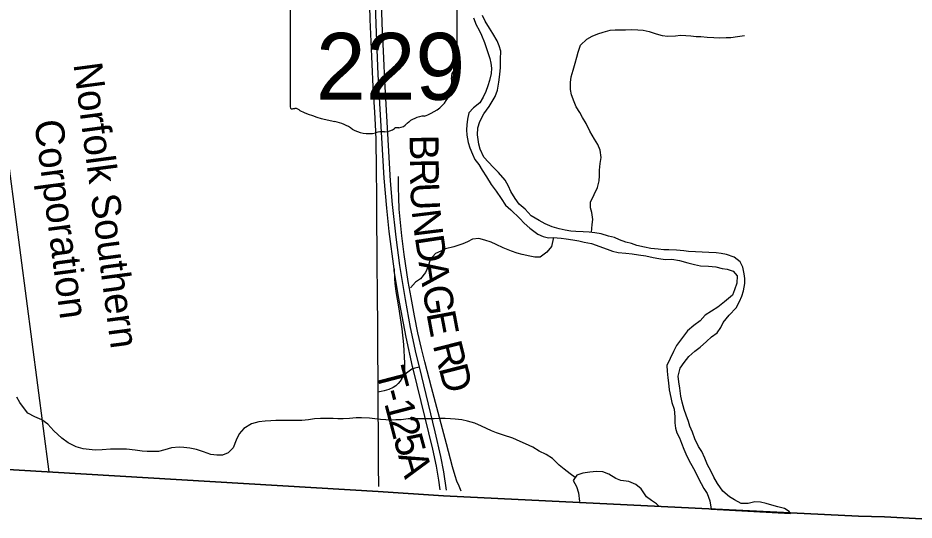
# Model space of a CAD drawing. Extents: x 1584893 to 1934202, y 663575 to 1091909.
# Drawn here: x 1804696 to 1814023, y 887388 to 892618 of the extents above; entities that cross this region are included whole.
import ezdxf

# ---------------------------------------------------------------- set-up
doc = ezdxf.new("R2010")
doc.units = 0
for name, color, linetype in [('GM_X_Adjacent_County', 7, 'Continuous'), ('GM_X_County', 7, 'Continuous'), ('GM_X_Interchange_Ramps', 7, 'Continuous'), ('GM_X_Major_River', 7, 'Continuous'), ('GM_X_Minor_River', 7, 'Continuous'), ('GM_X_Rail_Line', 7, 'Continuous'), ('GM_X_Rail_Line_Text', 7, 'Continuous'), ('GM_X_State_Location', 7, 'Continuous'), ('GM_X_State_Route', 7, 'Continuous'), ('GM_X_State_Shield', 7, 'Continuous'), ('GM_X_Township', 7, 'Continuous'), ('GM_X_Township_Road', 7, 'Continuous'), ('GM_X_Township_Road_Text', 7, 'Continuous'), ('GM_X_US_Route', 7, 'Continuous')]:
    doc.layers.add(name, color=color, linetype=linetype)

msp = doc.modelspace()

# ---------------------------------------------------------------- linework, layer by layer
at = {"layer": 'GM_X_Adjacent_County'}
msp.add_lwpolyline([(1760161.3, 891041.6), (1765804.4, 890576.9), (1771665.9, 890079.8), (1775268.9, 889747), (1775894.1, 889674), (1776031.5, 889657.9), (1778208.7, 889455.9), (1784657.2, 889013.6), (1789933.2, 888711.1), (1791146.1, 888682.4), (1797650.8, 888236.8), (1803655.1, 887971.5), (1808445, 887685), (1809126.3, 887642.5), (1809338.6, 887629.3), (1813443.3, 887428.9), (1813716.6, 887421.5), (1814360, 887388.3)], dxfattribs=at)
at = {"layer": 'GM_X_County'}
msp.add_lwpolyline([(1814360, 887388.3), (1813716.6, 887421.5), (1813443.3, 887428.9), (1809338.6, 887629.3), (1809126.3, 887642.5), (1808445, 887685), (1803655.1, 887971.5), (1797650.8, 888236.8), (1791146.1, 888682.4), (1789933.2, 888711.1), (1784657.2, 889013.6), (1778208.7, 889455.9), (1776031.5, 889657.9), (1775894.1, 889674), (1775268.9, 889747), (1771665.9, 890079.8), (1765804.4, 890576.9), (1760161.3, 891041.6)], dxfattribs=at)
at = {"layer": 'GM_X_Interchange_Ramps'}
for points in [[(1808611.1, 890004.3), (1808614.3, 889903.2), (1808617.8, 889853.2), (1808629.5, 889768.2), (1808656.8, 889609.2), (1808691, 889381.7), (1808707.8, 889218.1), (1808720.1, 889021.2), (1808719.6, 888955.5), (1808715.5, 888922.9), (1808706.6, 888891.3), (1808704.3, 888886.6), (1808692.3, 888861.7), (1808674.4, 888834.1), (1808653.1, 888809.1), (1808628.5, 888787.4), (1808601, 888769.4), (1808556.1, 888749), (1808509, 888734.3), (1808476.8, 888728), (1808441.7, 888721.2)], [(1808874.8, 888983.4), (1808857.4, 888978.3), (1808827.9, 888970.4), (1808809.5, 888963.6), (1808796.3, 888958.8), (1808781.1, 888950.7), (1808768, 888940.8), (1808740, 888917), (1808704.3, 888886.6)]]:
    msp.add_lwpolyline(points, dxfattribs=at)
at = {"layer": 'GM_X_Major_River'}
for points in [[(1809438, 892618.4), (1809467, 892545.7), (1809498.3, 892489.1), (1809519.6, 892438.6), (1809552.5, 892361.9), (1809573.7, 892299.4), (1809590.9, 892246.9), (1809606.2, 892196.6), (1809617.5, 892146.2), (1809624.7, 892093.9), (1809621.9, 892039.8), (1809604.8, 891967.8), (1809587.9, 891909.8), (1809565, 891851.9), (1809538.1, 891794.1), (1809503.1, 891732.4), (1809436.2, 891683.1), (1809389.3, 891629.6), (1809374.3, 891563.6), (1809367.4, 891505.5), (1809366.6, 891451.3), (1809369.8, 891397), (1809382.7, 891320.6), (1809397.9, 891266.2), (1809429, 891199.5), (1809452.3, 891145), (1809491.6, 891090.3), (1809526.8, 891033.6), (1809571.9, 890962.7), (1809620.8, 890881.7), (1809672, 890814.8), (1809724.9, 890735.8), (1809770.1, 890668.9), (1809827.5, 890617.9), (1809918.4, 890530.3), (1809963.8, 890479.5), (1810025.2, 890428.5), (1810108.5, 890367.1), (1810162.2, 890342.3), (1810218.2, 890329.4), (1810268.3, 890330.8), (1810348.5, 890325.6), (1810400.5, 890316.9), (1810472.5, 890307.8), (1810532.5, 890296.9), (1810588.5, 890284.1), (1810666.4, 890267), (1810828, 890210.5), (1810883.8, 890189.7), (1810941.7, 890174.8), (1811023.9, 890167.7), (1811087.9, 890162.7), (1811156, 890151.8), (1811230, 890138.7), (1811305.9, 890123.6), (1811365.9, 890112.7), (1811431.9, 890101.7), (1811502.1, 890104.8), (1811580.1, 890091.6), (1811668, 890068.3), (1811737.9, 890049.3), (1811801.9, 890036.3), (1811884.1, 890033.2), (1811960.1, 890024.1), (1812026.1, 890009.1), (1812076.1, 890002.4), (1812141.9, 889981.4), (1812183.3, 889930.7), (1812178.2, 889856.5), (1812153.1, 889784.6), (1812132.2, 889730.7), (1812051, 889661.5), (1811980, 889606.3), (1811915.2, 889563.1), (1811850.4, 889523.8), (1811797.4, 889464.4), (1811732.5, 889415.1), (1811663.6, 889359.9), (1811604.2, 889276.4)], [(1811972, 889337.5), (1812012.9, 889393.1), (1812035.8, 889445), (1812097.1, 889522.4), (1812170.4, 889599.7), (1812207.4, 889663.4), (1812230.3, 889721.3), (1812249.2, 889777.2), (1812260.4, 889853.3), (1812263.1, 889903.5), (1812255.8, 889953.7), (1812240.8, 890022.2), (1812211.6, 890078.8), (1812152.1, 890127.8), (1812072.3, 890155), (1812014.3, 890165.8), (1811964.3, 890170.6), (1811888.1, 890173.6), (1811816, 890178.7), (1811749.9, 890183.6), (1811675.8, 890186.6), (1811625.7, 890191.4), (1811549.6, 890198.4), (1811469.5, 890203.6), (1811419.4, 890204.3), (1811359.3, 890209.1), (1811283.3, 890218.2), (1811217.3, 890229.2), (1811137.3, 890248.4), (1811081.5, 890267.2), (1811021.6, 890284.1), (1810955.7, 890307.1), (1810903.9, 890329.9), (1810844, 890346.8), (1810766.2, 890368), (1810702.2, 890378.9), (1810642.1, 890385.8), (1810580, 890390.6), (1810503.9, 890393.7), (1810451.8, 890396.4), (1810391.8, 890407.3), (1810327.8, 890420.2), (1810258, 890443.3), (1810182.2, 890474.5), (1810122.6, 890507.4), (1810039.1, 890556.8), (1809973.9, 890625.9), (1809914.6, 890678.9), (1809871.3, 890737.7), (1809826.3, 890810.6), (1809803, 890865.1), (1809765.9, 890929.9), (1809698.9, 891009.1), (1809643.6, 891064.1), (1809592.2, 891115), (1809546.9, 891167.8), (1809506, 891250.6), (1809492.7, 891303), (1809480.1, 891399.5), (1809483.2, 891473.7), (1809504.2, 891539.7), (1809545.5, 891619.4), (1809600.8, 891696.9), (1809662.5, 891800.4), (1809687.5, 891866.3), (1809702.8, 891948.3), (1809712, 892028.5), (1809717.1, 892102.7), (1809720.4, 892188.9), (1809721.6, 892271.2), (1809706.4, 892325.6), (1809685.1, 892380.1), (1809640.1, 892455), (1809604.9, 892511.7), (1809557.8, 892582.6), (1809530.6, 892643.2)], [(1812738.6, 887456.1), (1812724, 887479), (1812672.8, 887509.2), (1812604.9, 887526.2), (1812543, 887543.2), (1812485.1, 887560), (1812425.1, 887574.9), (1812367, 887577.7), (1812294.6, 887562.7), (1812222.4, 887561.7), (1812152.8, 887600.8), (1812101.1, 887629.6), (1812031.9, 887690.8), (1811976.9, 887767.8), (1811937.7, 887834.6), (1811906.6, 887901.3), (1811873.5, 887964), (1811846.5, 888034.6), (1811813.4, 888101.3), (1811780.1, 888156), (1811741.1, 888234.8), (1811716.1, 888305.4), (1811688.9, 888366), (1811675.7, 888416.3), (1811650.5, 888480.9), (1811629.4, 888541.4), (1811608.4, 888616), (1811595.4, 888680.4), (1811584.5, 888760.8), (1811573.5, 888827.2), (1811566.3, 888887.5), (1811587.6, 888969.5), (1811630.6, 889029.2), (1811679.6, 889092.7), (1811740.6, 889146), (1811797.4, 889187.4), (1811862.4, 889246.7), (1811915.2, 889296.2), (1811972, 889337.5)], [(1811604.2, 889276.4), (1811549, 889206.9), (1811518, 889145.1), (1811482.8, 889071.4), (1811449.7, 888999.6), (1811452.8, 888939.3), (1811461.8, 888868.9), (1811467, 888816.7), (1811474, 888744.3), (1811490.8, 888663.8), (1811502.1, 888611.5), (1811527.1, 888542.9), (1811534, 888462.5), (1811533.1, 888400.3), (1811540.3, 888346), (1811555.6, 888295.6), (1811580.9, 888245.1), (1811602.1, 888190.6), (1811625.3, 888128), (1811646.6, 888077.5), (1811683.6, 888006.8), (1811711, 887956.2), (1811744.1, 887895.5), (1811775.2, 887828.9), (1811808.4, 887768.2), (1811835.8, 887717.6), (1811869.1, 887665), (1811896.3, 887588.4), (1811912.4, 887503)], [(1811912.4, 887503), (1812738.6, 887456.1)]]:
    msp.add_lwpolyline(points, dxfattribs=at)
at = {"layer": 'GM_X_Minor_River'}
for points in [[(1810666.5, 890382.9), (1810671.4, 890465.6), (1810678.2, 890519.7), (1810669.2, 890590.1), (1810653.9, 890640.5), (1810656.8, 890698.7), (1810692, 890778.4), (1810729.2, 890852.2), (1810744.3, 890922.2), (1810749.1, 890974.3), (1810747.9, 891032.6), (1810755, 891100.7), (1810765.9, 891162.8), (1810755, 891241.2), (1810731.8, 891299.7), (1810696.6, 891356.4), (1810649.7, 891439.4), (1810608.7, 891518.2), (1810571.6, 891580.9), (1810544.3, 891631.5), (1810505, 891690.3), (1810485.8, 891742.7), (1810456.8, 891817.4), (1810447.6, 891873.7), (1810446.6, 891944), (1810455.6, 892006.1), (1810474.6, 892074), (1810495.7, 892146), (1810514.7, 892207.9), (1810527.5, 892259.9), (1810552.7, 892333.8), (1810615.8, 892397.2), (1810672.3, 892426.5), (1810732.9, 892451.8), (1810787.3, 892469.1), (1810861.8, 892490.1), (1810912, 892495.4), (1810968.1, 892492.6), (1811018.2, 892493.9), (1811086.4, 892497), (1811146.5, 892492.2), (1811204.6, 892489.3), (1811266.6, 892476.4), (1811340.4, 892453.3), (1811402.4, 892436.4), (1811460.4, 892427.6), (1811540.7, 892432.5), (1811590.9, 892437.8), (1811647, 892435), (1811699.1, 892432.2), (1811755.1, 892425.4), (1811805.2, 892422.8), (1811869.3, 892417.8), (1811939.4, 892412.8), (1811993.5, 892412.1), (1812065.7, 892413.1), (1812115.8, 892412.4), (1812186.2, 892423.4), (1812256.5, 892436.5)], [(1810271.6, 890330.5), (1810250.9, 890236.7), (1810199.9, 890179.2), (1810133, 890125.9), (1810076.8, 890126.7), (1810022.9, 890137.5), (1809944.9, 890152.6), (1809893, 890167.4), (1809833.1, 890188.3), (1809747.4, 890223.7), (1809673.8, 890258.8), (1809620, 890281.6), (1809554.1, 890302.6), (1809492.2, 890319.5), (1809425.9, 890312.4), (1809375.4, 890287), (1809325, 890265.7), (1809232.3, 890234.9), (1809147.7, 890212), (1809097.2, 890188.6), (1809042.7, 890163.3), (1808985.7, 890101.8), (1808964.6, 890029.9), (1808937.6, 889968), (1808884.4, 889900.5), (1808833.8, 889867.1), (1808780.8, 889805.6)], [(1810496.3, 887833.5), (1810444.5, 887871.6), (1810381, 887918.6), (1810329.5, 887961.5), (1810258.4, 888030.7), (1810192.8, 888069.8), (1810121.1, 888106.9), (1810055.6, 888148), (1809979.9, 888181.1), (1809924.1, 888208), (1809848.4, 888241.2), (1809750.6, 888272.7), (1809676.8, 888295.8), (1809625, 888316.6), (1809573.2, 888341.4), (1809521.4, 888366.2), (1809451.7, 888397.3), (1809375.8, 888418.4), (1809317.9, 888431.3), (1809247.8, 888438.3), (1809197.7, 888443), (1809141.7, 888445.8), (1809089.5, 888446.5), (1809027.3, 888443.4), (1808963.1, 888442.2), (1808818.8, 888444.3), (1808756.6, 888441.1), (1808686.3, 888434.1), (1808628.1, 888430.9), (1808574, 888429.6), (1808523.9, 888432.3), (1808469.8, 888437.1), (1808411.8, 888443.9), (1808353.7, 888448.8), (1808271.6, 888453.9), (1808215.4, 888452.7), (1808147.1, 888445.7), (1808082.9, 888444.5), (1808026.8, 888443.3), (1807976.7, 888446), (1807898.5, 888445.1), (1807844.3, 888445.9), (1807784.2, 888442.7), (1807719.9, 888433.6), (1807649.6, 888426.5), (1807567.3, 888425.7), (1807499.2, 888426.6), (1807435, 888425.5), (1807378.8, 888424.3), (1807328.7, 888423), (1807270.5, 888419.8), (1807204.2, 888410.7), (1807127.7, 888389.7), (1807048.8, 888342.6), (1806997.8, 888285.1), (1806966.8, 888219.3), (1806935.5, 888141.5), (1806884.6, 888088), (1806826.1, 888064.7), (1806766, 888063.6), (1806703.9, 888070.4), (1806626.1, 888099.6), (1806554.3, 888124.7), (1806486.3, 888135.7), (1806424.3, 888142.6), (1806374.2, 888147.3), (1806293.9, 888142.4), (1806225.4, 888121.3), (1806161, 888104.2), (1806102.8, 888101), (1806042.7, 888101.8), (1805988.6, 888104.6), (1805916.6, 888117.6), (1805826.5, 888126.9), (1805772.4, 888127.7), (1805722.2, 888126.4), (1805660.1, 888125.2), (1805571.8, 888120.4), (1805501.5, 888117.4), (1805437.4, 888122.3), (1805375.4, 888131.2), (1805301.5, 888152.3), (1805219.9, 888191.6), (1805152.5, 888242.7), (1805069.4, 888318.2), (1805008.2, 888387.3), (1804944.7, 888432.3), (1804873, 888463.4), (1804799.4, 888502.6), (1804754.1, 888559.4), (1804716.8, 888612.2), (1804685.6, 888668.8)], [(1811367.9, 887534), (1811342.1, 887557.9), (1811290.5, 887592.8), (1811238.9, 887629.6), (1811182, 887712.7), (1811128.5, 887757.6), (1811052.8, 887790.8), (1810970.8, 887802), (1810919, 887822.8), (1810847.5, 887867.9), (1810783.6, 887890.9), (1810719.5, 887893.8), (1810649.2, 887886.8), (1810574.9, 887877.8), (1810512.4, 887856.6), (1810473.5, 887800.9), (1810508.7, 887738.2), (1810531.8, 887673.7), (1810541.5, 887580.9)]]:
    msp.add_lwpolyline(points, dxfattribs=at)
at = {"layer": 'GM_X_Rail_Line'}
msp.add_lwpolyline([(1805021.2, 887892.5), (1804486.1, 891953.9), (1804003.2, 895608.6), (1803961.2, 895915.8), (1803923.7, 896195.6), (1803900.8, 896361.4), (1803878.6, 896512.8), (1803854.2, 896661), (1803822.9, 896810.8), (1803790.7, 896950.7), (1803759.4, 897065.4), (1803720.4, 897203.7), (1803662.3, 897391.7), (1803608.8, 897569), (1803427.7, 898158.3), (1802836.3, 900071.8), (1801234.3, 905259.6), (1799407.7, 911173.8), (1798749.4, 913306.4), (1797936.3, 915934.2), (1797744, 916556.4), (1796673.7, 920025.1)], dxfattribs=at)
at = {"layer": 'GM_X_State_Route'}
for points in [[(1808344.9, 893264.9), (1808352.2, 892891.9), (1808358.4, 892601.7), (1808367.7, 892373.4), (1808390.1, 891900.2), (1808406, 891637.5), (1808416.2, 891437.1), (1808419.9, 891344.2), (1808420.9, 891291.4), (1808424.6, 891103), (1808425.6, 890970.1)], [(1808425.6, 890970.1), (1808426.6, 890831.1), (1808428.5, 890621.3), (1808429.4, 890438.5), (1808431.3, 890260.3), (1808433.2, 890078.4), (1808435.2, 889723), (1808438.5, 889415.7), (1808439.7, 889104), (1808441.8, 888905.4), (1808441.5, 888743.1), (1808441.7, 888721.2), (1808443.5, 888562.6), (1808443.6, 888520.3)], [(1808443.6, 888520.3), (1808444.5, 888308.8)], [(1808444.5, 888308.8), (1808444.8, 888241), (1808444.8, 887956.1), (1808447.8, 887738)]]:
    msp.add_lwpolyline(points, dxfattribs=at)
at = {"layer": 'GM_X_State_Shield'}
for p, q in [((1809268.3, 892239.3), (1809268.3, 892792)), ((1807528.1, 892747.6), (1807528.1, 891691)), ((1809268.1, 892239.4), (1809268.3, 892239.3))]:
    msp.add_line(p, q, dxfattribs=at)
for centre, major_axis, start_param, end_param in [((1809263.8, 892198.7), (30, 0), 1.883978, 3.671073), ((1809247.6, 892237.1), (20.7, 0), 5.05454, 6.418171), ((1809073.1, 892128.8), (180, 0), 5.934695, 6.695948), ((1809337.7, 892007.9), (130.9, 0), 2.387724, 3.262537), ((1808751.8, 891937.6), (461.6, 0), 5.101752, 6.440018), ((1807548.2, 891688.7), (20.3, 0), 3.00124, 4.508301), ((1807551.3, 891796.8), (155.2, 0), 4.665946, 4.897461), ((1807583.1, 891630), (56, 0), 0.519207, 1.627899), ((1808289.7, 892579.4), (1332.7, 0), 4.195997, 4.488961), ((1808946.4, 891394.3), (252.8, 0), 1.647645, 2.488434), ((1807892.3, 891216.3), (417, 0), 0.823519, 1.323587), ((1808343.3, 891624.8), (264.6, 0), 4.026481, 4.996735), ((1808515.5, 891545.7), (141, 0), 4.691044, 5.507374), ((1808643.1, 891443.3), (39.7, 0), 1.147584, 2.315152), ((1808626.1, 891588.6), (149.1, 0), 4.937069, 5.64225), ((1808496.2, 891259.5), (217.4, 0), 1.495662, 1.94098)]:
    msp.add_ellipse(centre, major_axis=major_axis, ratio=0.8, start_param=start_param, end_param=end_param, dxfattribs=at)
at = {"layer": 'GM_X_Township'}
msp.add_lwpolyline([(1814360, 887388.3), (1813716.6, 887421.5), (1813443.3, 887428.9), (1809338.6, 887629.3), (1809126.3, 887642.5), (1808445, 887685), (1803655.1, 887971.5), (1797650.8, 888236.8), (1797679.2, 888792.3), (1797956.5, 892833.2), (1798002.2, 893510), (1798208.2, 896482), (1798438.2, 899802.5), (1798464.8, 900237.4), (1798577, 901966.4), (1796834.2, 901749.1), (1796690.9, 901747.6), (1793307.8, 901347)], dxfattribs=at)
at = {"layer": 'GM_X_Township_Road'}
msp.add_lwpolyline([(1809310.4, 887689.9), (1809287.4, 887740.6), (1809265.2, 887794.1), (1809248, 887848.7), (1809220.7, 887943.2), (1809158.4, 888180.9), (1809001.7, 888769.6), (1808932.3, 889035.5), (1808895.6, 889176), (1808858.7, 889338), (1808823.1, 889514.6), (1808787.9, 889708), (1808759.3, 889874.1), (1808716.9, 890153.3), (1808692.1, 890348.6), (1808673.5, 890523.5), (1808665.5, 890625.2), (1808660.1, 890748), (1808657.5, 890850.5), (1808656.6, 890911.5), (1808656.6, 890968)], dxfattribs=at)
at = {"layer": 'GM_X_US_Route'}
for points in [[(1809157.9, 887698.3), (1809129.3, 887891.3), (1809097.7, 888052.1), (1809037.3, 888307.4), (1808874.8, 888983.4), (1808841.3, 889120.9), (1808782.9, 889393.7), (1808728.3, 889684.1), (1808671.3, 890040.6), (1808632.2, 890333.5), (1808594.9, 890676.1), (1808575.2, 890921.5), (1808516.2, 891963.6), (1808504.8, 892197.4), (1808488.5, 892559.9), (1808478.3, 892953.6), (1808471.5, 893413), (1808471.8, 893856.1), (1808482.1, 894249.7), (1808489, 894577.6), (1808487.5, 894675.1), (1808484.2, 894778), (1808482.1, 894832.1), (1808478.7, 894878.3)], [(1809089.9, 887702.2), (1809076.1, 887805.5), (1809067.8, 887865.3), (1809051.2, 887951.3), (1809013, 888127.8), (1808809.5, 888963.6), (1808803.4, 888988.6), (1808735.4, 889292.7), (1808655.8, 889711.6), (1808613.3, 889987.1), (1808611.1, 890004.3), (1808560.6, 890393.7), (1808534.8, 890638.3), (1808508.6, 890948.8), (1808447, 892029.8), (1808423.1, 892554.1), (1808411, 892980.4)]]:
    msp.add_lwpolyline(points, dxfattribs=at)

# ---------------------------------------------------------------- texts
at = {"layer": 'GM_X_Rail_Line_Text'}
for s, rotation, p in [('Norfolk Southern', 277.50744, (1805273.3, 892136.7)), ('Corporation', 277.49584, (1804865.4, 891541.3))]:
    msp.add_text(s, height=299, rotation=rotation, dxfattribs=at).set_placement(p)
at = {"layer": 'GM_X_State_Location'}
for s in ['r', 's']:
    msp.add_text(s, height=1, dxfattribs=at).set_placement((1808378.6, 892149.1))
msp.add_text('229', height=1, rotation=0.00001, dxfattribs=at).set_placement((1808025.7, 892076.3))
at = {"layer": 'GM_X_State_Shield'}
msp.add_text('229', height=696.1, dxfattribs=at).set_placement((1807798, 891765.5))
at = {"layer": 'GM_X_Township_Road_Text'}
for s, rotation, p in [('B', 270.63622, (1808773, 891400.7)), ('R', 270.65421, (1808775.8, 891154.3)), ('U', 272.60626, (1808778.9, 890896.7)), ('N', 276.91654, (1808792.9, 890608.4)), ('D', 278.56512, (1808826, 890337)), ('A', 278.5559, (1808865.3, 890076)), ('G', 278.69098, (1808904.7, 889814.1)), ('E', 280.69987, (1808946.6, 889541.8)), ('R', 284.18913, (1809012.9, 889211.8)), ('T', 284.6308, (1808418.9, 888942.3)), ('D', 284.45786, (1809073.7, 888971.4)), ('-', 284.64651, (1808475.6, 888725.1)), ('1', 284.68577, (1808506.8, 888605.7)), ('2', 284.80512, (1808553.9, 888426.3)), ('5', 285.10256, (1808601.5, 888246)), ('A', 286.09898, (1808651.2, 888062.1))]:
    msp.add_text(s, height=300, rotation=rotation, dxfattribs=at).set_placement(p)

doc.saveas('drawing.dxf')
